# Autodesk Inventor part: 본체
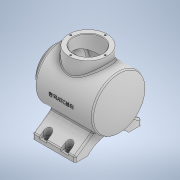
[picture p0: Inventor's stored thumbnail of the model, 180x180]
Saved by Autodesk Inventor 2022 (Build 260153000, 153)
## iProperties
Created: 2023-04
Part Number: 본체
Material: 일반
Document SubType Name: Modeling
Designer: Admin
Density: 1 g/cm^3
Appearance: 기본값
Author: Admin
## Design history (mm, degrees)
sketch "스케치2"
  geometry: L1 (0, -10.134)-(0, 60.805) reference; L2 (-38.908, 0)-(149.45, 0) reference; L3 (0, 0)-(108, 0); L4 (108, 0)-(108, 50); L5 (108, 50)-(0, 50); L6 (0, 50)-(0, 0); L7 (108, 0)-(119.664, 0); L8 (0, 0)-(-12, 0); L9 (-12, 0)-(-12, 36); L10 (-12, 36)-(0, 36); L11 (0, 36)-(0, 0); A1 r 113 centre (6.664, 0) between (119.664, 0) and (108, 50); 2 further points
  constraints: 18 end point, 4 parallel, 4 point on line, 2 horizontal, 2 perpendicular, 2 point on circle, 1 centre point, 1 collinear
  dimensions: "d0" = 100 diameter of L5 L2; "d2" = 113 radius of A1; "d3" = 12 distance of L9.end L10.end; "d4" = 72 diameter of L10 L2; "d116" = 120 distance from line of L4.end L9
revolve "회전1" sketch "스케치2" stored, may be unused: angle "d5" = 90 deg
node "작업 평면2"
sketch "스케치6"
  geometry: L1 (0, -144.515)-(0, 82.419) reference; L2 (-86.8, 0)-(86.8, 0) reference; L3 (-26.694, -42.278)-(-62, -67); L4 (-62, -67)-(-62, -77); L5 (-62, -77)-(-38.5, -77); L6 (-38.5, -77)-(0, -77); L7 (26.694, -42.278)-(62, -67); L8 (62, -67)-(62, -77); L9 (62, -77)-(38.5, -77); A1 r 52.096 centre (0, -112.096) between (0, -60) and (-38.5, -77); A2 r 52.096 centre (0, -112.096) between (38.5, -77) and (0, -60); 3 further points
  constraints: 14 end point, 4 point on circle, 4 symmetric about line, 3 point on line, 2 centre point, 2 perpendicular, 1 vertical, 3 other
  dimensions: "d26" = 10 distance of L3.end L4.end; "d27" = 38.5 distance from line of L1 L5.end; "d28" = 55 deg angle of L4 L3; "d29" = 77 distance between parallel lines of L5 L2; "d30" = 17 distance of L6.end A1.start; "d31" = 124 distance between parallel lines of L8 L4
extrude "돌출1" join sketch "스케치6" distance "d32" = 80; taper "d33" = 0 deg
node "작업 평면3"
sketch "스케치7"
  geometry: L1 (31.6, 0)-(-105.6, 0) reference; L2 (0, -50.4)-(0, 50.4) reference; L3 (12, 36)-(12, -36) reference; C1 r 36 at (-50, 0); 1 further point
  constraints: 1 centre point, 1 point on line
  dimensions: "d36" = 72 diameter of C1; "d38" = 62 distance from line of C1.centre L3
extrude "돌출2" join sketch "스케치7" stored distance "d39" = 10; taper "d40" = 0 deg
sketch "스케치8"
  geometry: C1 r 36 at (0, 0) reference; C2 r 27 at (0, 0); 1 further point
  constraints: 1 centre point, 1 coincident
  dimensions: "d41" = 54 diameter of C2
extrude "돌출3" cut sketch "스케치8" distance "d42" = 65; taper "d43" = 0 deg
sketch "스케치9"
  geometry: L1 (-38.333, 0)-(145.997, 0) reference; L2 (-12, -36)-(-12, 36) reference; L3 (-12, 0)-(7, 0); L4 (7, 0)-(7, 27); L5 (7, 27)-(-12, 27); L6 (-12, 27)-(-12, 0); L7 (7, 0)-(103.876, 0); L8 (103.55, 43)-(7, 43); L9 (7, 43)-(7, 0); L10 (103.876, 0)-(113.757, 0); A1 r 113 centre (6.664, 0) between (108, -50) and (108, 50) reference; A2 r 106 centre (6.664, 0) between (112.664, 0) and (103.55, 43); 4 further points
  constraints: 16 end point, 3 parallel, 2 horizontal, 2 point on circle, 2 point on line, 1 centre point, 1 midpoint, 1 perpendicular
  dimensions: "d44" = 7 radial gap between concentric circles of A1 A2; "d45" = 86 diameter of L8 L1; "d46" = 19 distance of L4.end L5.end; "d47" = 54 diameter of L5 L1
revolve "회전2" sketch "스케치9" stored, may be unused: angle "d48" = 90 deg
node "작업 평면5"
sketch "스케치11"
  geometry: L1 (0, 23.5)-(80, 23.5) reference; L2 (0, 0)-(0, 23.5) reference; L3 (13, 15.5)-(27, 15.5); L4 (27, 15.5)-(27, 23.5); L5 (27, 23.5)-(13, 23.5); L6 (13, 23.5)-(13, 15.5); L7 (53, 15.5)-(67, 15.5); L8 (67, 15.5)-(67, 23.5); L9 (67, 23.5)-(53, 23.5); L10 (53, 23.5)-(53, 15.5); L11 (-46.333, -38.5)-(137.997, -38.5) reference; L12 (27, -100.5)-(13, -100.5); L13 (27, -92.5)-(27, -100.5); L14 (13, -100.5)-(13, -92.5); L15 (53, -100.5)-(53, -92.5); L16 (67, -100.5)-(53, -100.5); L17 (67, -92.5)-(67, -100.5); A1 r 7 centre (20, 15.5) between (13, 15.5) and (27, 15.5); A2 r 7 centre (60, 15.5) between (53, 15.5) and (67, 15.5); A3 r 7 centre (20, -92.5) between (27, -92.5) and (13, -92.5); A4 r 7 centre (60, -92.5) between (67, -92.5) and (53, -92.5); 1 further point
  constraints: 28 end point, 10 symmetric about line, 8 point on circle, 4 centre point, 4 parallel, 2 horizontal, 2 midpoint, 2 perpendicular, 2 point on line, 2 other
  dimensions: "d59" = 14 distance of L3.start L3.end; "d60" = 20 distance from line of A1.centre L2; "d61" = 8 distance from line of L1 A1.centre; "d62" = 14 distance of L7.start L7.end; "d63" = 40 distance of A2.centre A1.centre; "d64" = 8 distance between parallel lines of L1 L7
extrude "돌출4" cut sketch "스케치11" distance "d65" = 20; taper "d66" = 0 deg
sketch "스케치12"
  geometry: A1 r 7 centre (20, -15.5) between (27, -15.5) and (13, -15.5) reference; A2 r 7 centre (60, -15.5) between (67, -15.5) and (53, -15.5) reference; A3 r 7 centre (20, 92.5) between (13, 92.5) and (27, 92.5) reference; A4 r 7 centre (60, 92.5) between (53, 92.5) and (67, 92.5) reference; 5 further points
  constraints: 4 coincident
hole "구멍1" sketch "스케치12" at (20, -15.5), (60, -15.5), (20, 92.5), (60, 92.5) diameter "d67" = 9; stored, may be unused: countersink angle "d71" = 90 deg, drill point angle "d73" = 118 deg; dims "d68" = 9, "d69" = 4, "d70" = 2, "d72" = 6
fillet "모깎기1" dims "d74" = 3
fillet "모깎기2" dims "d75" = 3
fillet "모깎기3" dims "d76" = 3
fillet "모깎기4" dims "d77" = 3
sketch "스케치13" dims "d78" = 65
  geometry: L1 (0, 70)-(0, -70) reference; 6 further points
  constraints: 1 coincident, 1 point on line, 1 vertical alignment, 7 other
  dimensions: "d81" = 360 deg dimension on point (0, 0) point (0, -32.5) (derived)
hole "구멍2" sketch "스케치13" at (0, -32.5), (32.5, 0), (0, 32.5), (-32.5, 0) diameter "d83" = 3.242; stored, may be unused: countersink angle "d87" = 90 deg, drill point angle "d89" = 118 deg; dims "d84" = 8, "d85" = 4, "d86" = 2, "d88" = 10
sketch "스케치14" dims "d90" = 65
  geometry: L1 (-88.333, 0)-(95.997, 0) reference; C1 r 27 at (0, 0) reference; 6 further points
  constraints: 1 coincident, 1 horizontal alignment, 1 point on line, 7 other
  dimensions: "d93" = 360 deg dimension on point (0, 0) point (-32.5, 0) (derived)
hole "구멍3" sketch "스케치14" at (-32.5, 0), (0, -32.5), (32.5, 0), (0, 32.5) diameter "d95" = 3.242; stored, may be unused: countersink angle "d99" = 90 deg, drill point angle "d101" = 118 deg; dims "d96" = 8, "d97" = 4, "d98" = 2, "d100" = 10
chamfer "모따기1" distance "d102" = 1; stored, may be unused: second distance "d103" = 2, angle "d104" = 45 deg
chamfer "모따기2" distance "d105" = 1; stored, may be unused: second distance "d106" = 2, angle "d107" = 45 deg
fillet "모깎기5" dims "d108" = 3
node "작업 평면6"
sketch "스케치15"
  geometry: L1 (-12, -36)-(-12, 36) reference; L2 (-24.4, 0)-(62.4, 0) reference; 2 further points
  constraints: 1 other
  dimensions: "d110" = 62 distance from line of point (50, 0) L1; "d111" = 0 distance from line of L2 point (50, 0)
feature "엠보싱1" sketch "스케치15" dims "d26" = 10, "d112" = 0.5, "d113" = 0
fillet "모깎기6" dims "d114" = 3
node "솔리드1"
feature "A9D066F2-1C7D-4E18-AEED-F7BC21143FA4" dims "d67" = 9, "d68" = 9, "d69" = 4, "d70" = 2, "d71" = 90 deg, "d72" = 6, "d73" = 118 deg
other parameters: "d34" = 65, "d54" = -6, "d109" = 125
